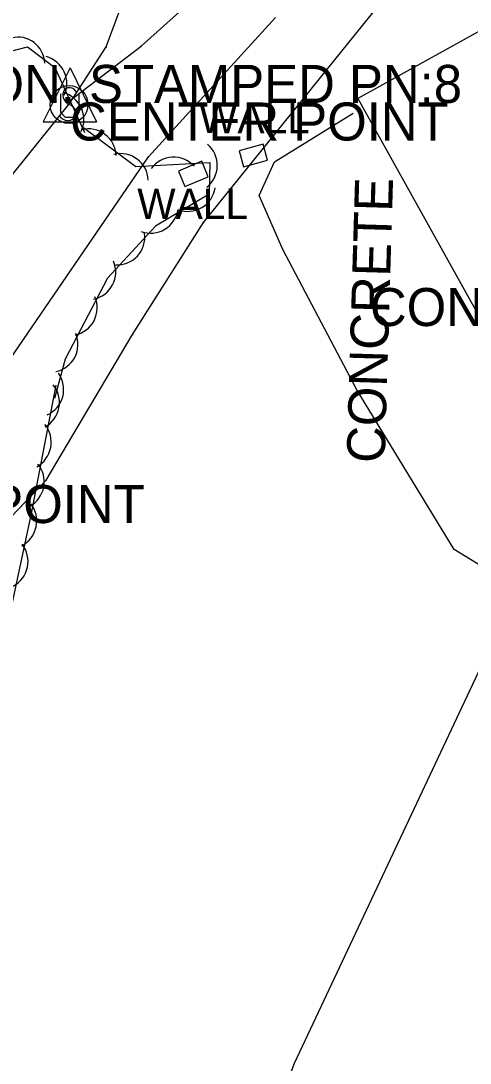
# Model space of a CAD drawing. Extents: x 978516 to 993312, y 1836504 to 1846212.
# Drawn here: x 992764.3 to 992823.3, y 1840378.8 to 1840515.9 of the extents above; entities that cross this region are included whole.
import ezdxf

# ---------------------------------------------------------------- set-up
doc = ezdxf.new("R2010")
doc.units = 0
for name, color, linetype in [('S_BUILDING', 7, 'Continuous'), ('S_FIBER_OPTIC_CABLE', 7, 'Continuous'), ('S_GAS_UTILITIES', 7, 'Continuous'), ('S_PARKING', 7, 'Continuous'), ('S_PARKING_ANNOT', 7, 'Continuous'), ('S_PRIMARY_CTL_ANNOT', 7, 'Continuous'), ('S_SIGN', 7, 'Continuous'), ('S_SURVEY_TEXT_ANNOT', 7, 'Continuous'), ('S_TREE', 7, 'Continuous'), ('S_UNDERGROUND_CABLE', 7, 'Continuous'), ('S_UTILITY_POLE_ANNOT', 7, 'Continuous'), ('S_UTL_PT_SYM', 7, 'Continuous'), ('S_WALL', 7, 'Continuous'), ('S_WALL_ANNOT', 7, 'Continuous')]:
    doc.layers.add(name, color=color, linetype=linetype)

msp = doc.modelspace()

# ---------------------------------------------------------------- linework, layer by layer
at = {"layer": 'S_BUILDING'}
msp.add_lwpolyline([(992808.57, 1840505.65), (992829.2, 1840468.57), (992857.68, 1840484.4), (992837.04, 1840521.49)], close=True, dxfattribs=at)
at = {"layer": 'S_FIBER_OPTIC_CABLE'}
for p, q in [((992788.25, 1840489.33), (992820.65, 1840529.49)), ((992781.05, 1840497.97), (992797.72, 1840516.31)), ((992737.56, 1840434.53), (992781.05, 1840497.97)), ((992778.92, 1840474.59), (992788.25, 1840489.33)), ((992767.58, 1840455.45), (992778.92, 1840474.59)), ((992734.08, 1840420.45), (992767.58, 1840455.45))]:
    msp.add_line(p, q, dxfattribs=at)
at = {"layer": 'S_GAS_UTILITIES'}
for p, q in [((992780.08, 1840512.54), (992800.28, 1840530.72)), ((992775.47, 1840512.42), (992781.54, 1840528.78)), ((992770.47, 1840505.22), (992780.08, 1840512.54)), ((992770.68, 1840505.03), (992775.47, 1840512.42)), ((992725.65, 1840448.94), (992770.68, 1840505.03))]:
    msp.add_line(p, q, dxfattribs=at)
at = {"layer": 'S_PARKING'}
for points in [[(992808.43, 1840467.32), (992798.68, 1840485.79), (992795.57, 1840492.87), (992797.59, 1840497.3), (992807.95, 1840503.71)], [(992758.32, 1840120.5), (992753.69, 1840120.82), (992739.14, 1840121.77), (992739.62, 1840142.03), (992736.36, 1840165.11), (992734.9, 1840202.15), (992745.57, 1840240.66), (992756.26, 1840265.48), (992768.16, 1840297.32), (992783.66, 1840334.94), (992800.24, 1840378.79), (992826.11, 1840433.86), (992833.55, 1840438.81), (992821.24, 1840446.35), (992808.43, 1840467.32)]]:
    msp.add_lwpolyline(points, dxfattribs=at)
at = {"layer": 'S_SIGN'}
msp.add_circle((992770.59, 1840504.85), 2.49, dxfattribs=at)
for centre, radius, start, end in [((992770.67, 1840506.12), 0.95, 16.5258, 156.8957), ((992771.28, 1840506.18), 1.5, 167.1196, 241.9813), ((992770.18, 1840503.51), 1.4, 358.6529, 73.7063), ((992770.44, 1840504.03), 1.28, 204.641, 335.359)]:
    msp.add_arc(centre, radius, start, end, dxfattribs=at)
at = {"layer": 'S_TREE'}
for points in [[(992752.51, 1840465.02), (992749.82, 1840486.19), (992758.82, 1840510.8), (992765.12, 1840512.46), (992768.71, 1840509.72), (992772.63, 1840501.19)], [(992772.47, 1840501.83), (992779.36, 1840496.69), (992789.08, 1840497.21), (992789, 1840493.07), (992781.97, 1840488.87), (992775.66, 1840482), (992770.07, 1840471.37), (992768.68, 1840466.21)], [(992768.84, 1840467.93), (992765.62, 1840451.06), (992758.49, 1840417.97), (992731.36, 1840335.88)]]:
    msp.add_lwpolyline(points, dxfattribs=at)
for centre, major_axis, ratio, start_param, end_param in [((992763.95, 1840510.07), (0.25, 3.63), 0.946906, 4.8381, 6.611301), ((992766.68, 1840507.71), (-3.04, 2.01), 0.975253, 3.259289, 5.03249), ((992768.93, 1840502.97), (-3.04, 2.01), 0.975253, 3.259289, 5.03249), ((992773.14, 1840498.01), (-2.29, -2.83), 0.999526, 2.294697, 4.067898), ((992786.44, 1840496.84), (0.06, 3.64), 0.999939, 3.825789, 5.598989), ((992777.37, 1840494.76), (-2.29, -2.83), 0.999526, 2.294697, 4.067898), ((992784.34, 1840494.29), (-3.64, -0.19), 0.999948, 3.825789, 5.598989), ((992786.18, 1840494.44), (3.2, 1.75), 0.999904, 3.862776, 5.635977), ((992781.31, 1840491.58), (3.2, 1.75), 0.999904, 3.862776, 5.635977), ((992776.91, 1840487.4), (2.85, 2.27), 0.999892, 3.979309, 5.752509), ((992773.09, 1840482.83), (1.93, 3.09), 0.9999, 3.899853, 5.673053), ((992770.65, 1840478.12), (1.93, 3.09), 0.9999, 3.899853, 5.673053), ((992768.12, 1840473.3), (1.93, 3.09), 0.9999, 3.899853, 5.673053), ((992766.24, 1840467.38), (0.95, 3.52), 0.999915, 3.825789, 5.598989), ((992765.75, 1840465.65), (0.68, 3.58), 0.981683, 3.825789, 5.598989), ((992764.67, 1840460.42), (0.68, 3.58), 0.981683, 3.825789, 5.598989), ((992763.75, 1840455.22), (0.68, 3.58), 0.981683, 3.825789, 5.598989), ((992762.77, 1840450.06), (1, 3.5), 0.981544, 3.893975, 5.667176), ((992761.62, 1840444.74), (1, 3.5), 0.981544, 3.893975, 5.667176)]:
    msp.add_ellipse(centre, major_axis=major_axis, ratio=ratio, start_param=start_param, end_param=end_param, dxfattribs=at)
at = {"layer": 'S_UNDERGROUND_CABLE'}
for p, q in [((992770.72, 1840509.66), (992767.2, 1840502.57)), ((992770.72, 1840509.66), (992774.21, 1840502.57)), ((992769.52, 1840503.81), (992769.52, 1840506.25)), ((992771.89, 1840506.25), (992771.89, 1840503.81)), ((992770.14, 1840503.15), (992769.52, 1840503.81)), ((992771.34, 1840503.15), (992770.14, 1840503.15)), ((992771.89, 1840503.81), (992771.34, 1840503.15)), ((992767.2, 1840502.57), (992774.21, 1840502.57))]:
    msp.add_line(p, q, dxfattribs=at)
at = {"layer": 'S_UTL_PT_SYM'}
for points in [[(992775.47, 1840512.42), (992775.47, 1840512.47), (992775.47, 1840512.42), (992775.42, 1840512.42), (992775.47, 1840512.42), (992775.47, 1840512.37), (992775.47, 1840512.42), (992775.52, 1840512.42)], [(992780.08, 1840512.54), (992780.08, 1840512.59), (992780.08, 1840512.54), (992780.03, 1840512.54), (992780.08, 1840512.54), (992780.08, 1840512.49), (992780.08, 1840512.54), (992780.13, 1840512.54)], [(992770.47, 1840505.22), (992770.47, 1840505.27), (992770.47, 1840505.22), (992770.42, 1840505.22), (992770.47, 1840505.22), (992770.47, 1840505.17), (992770.47, 1840505.22), (992770.52, 1840505.22)], [(992770.68, 1840505.03), (992770.68, 1840505.08), (992770.68, 1840505.03), (992770.63, 1840505.03), (992770.68, 1840505.03), (992770.68, 1840504.98), (992770.68, 1840505.03), (992770.73, 1840505.03)], [(992781.05, 1840497.97), (992781.05, 1840498.02), (992781.05, 1840497.97), (992781, 1840497.97), (992781.05, 1840497.97), (992781.05, 1840497.92), (992781.05, 1840497.97), (992781.1, 1840497.97)], [(992788.25, 1840489.33), (992788.25, 1840489.38), (992788.25, 1840489.33), (992788.2, 1840489.33), (992788.25, 1840489.33), (992788.25, 1840489.28), (992788.25, 1840489.33), (992788.3, 1840489.33)], [(992778.92, 1840474.59), (992778.92, 1840474.64), (992778.92, 1840474.59), (992778.87, 1840474.59), (992778.92, 1840474.59), (992778.92, 1840474.54), (992778.92, 1840474.59), (992778.97, 1840474.59)], [(992767.58, 1840455.45), (992767.58, 1840455.5), (992767.58, 1840455.45), (992767.53, 1840455.45), (992767.58, 1840455.45), (992767.58, 1840455.4), (992767.58, 1840455.45), (992767.63, 1840455.45)]]:
    msp.add_lwpolyline(points, dxfattribs=at)
at = {"layer": 'S_WALL'}
for points in [[(992796.11, 1840499.64), (992792.95, 1840498.76), (992793.54, 1840496.67), (992796.69, 1840497.55)], [(992788.05, 1840497.39), (992784.96, 1840496.11), (992785.81, 1840494.06), (992788.9, 1840495.34)]]:
    msp.add_lwpolyline(points, close=True, dxfattribs=at)

# ---------------------------------------------------------------- texts
at = {"layer": 'S_PARKING_ANNOT'}
msp.add_text('CONCRETE', height=5, rotation=88.2942, dxfattribs=at).set_placement((992812.08, 1840457.66))
at = {"layer": 'S_PRIMARY_CTL_ANNOT'}
msp.add_text('PD:ARDOT STD. MON. STAMPED PN:8', height=5, dxfattribs=at).set_placement((992700.41, 1840505.06))
at = {"layer": 'S_SURVEY_TEXT_ANNOT'}
msp.add_text('CONC', height=5, dxfattribs=at).set_placement((992810.15, 1840475.72))
at = {"layer": 'S_UTILITY_POLE_ANNOT'}
for p in [(992770.72, 1840500.12), (992730.76, 1840449.81)]:
    msp.add_text('CENTER POINT', height=5, dxfattribs=at).set_placement(p)
at = {"layer": 'S_WALL_ANNOT'}
for rotation, p in [(359.9123, (992787.68, 1840501.09)), (0.0512, (992779.56, 1840489.8))]:
    msp.add_text('WALL', height=4, rotation=rotation, dxfattribs=at).set_placement(p)

doc.saveas('drawing.dxf')
